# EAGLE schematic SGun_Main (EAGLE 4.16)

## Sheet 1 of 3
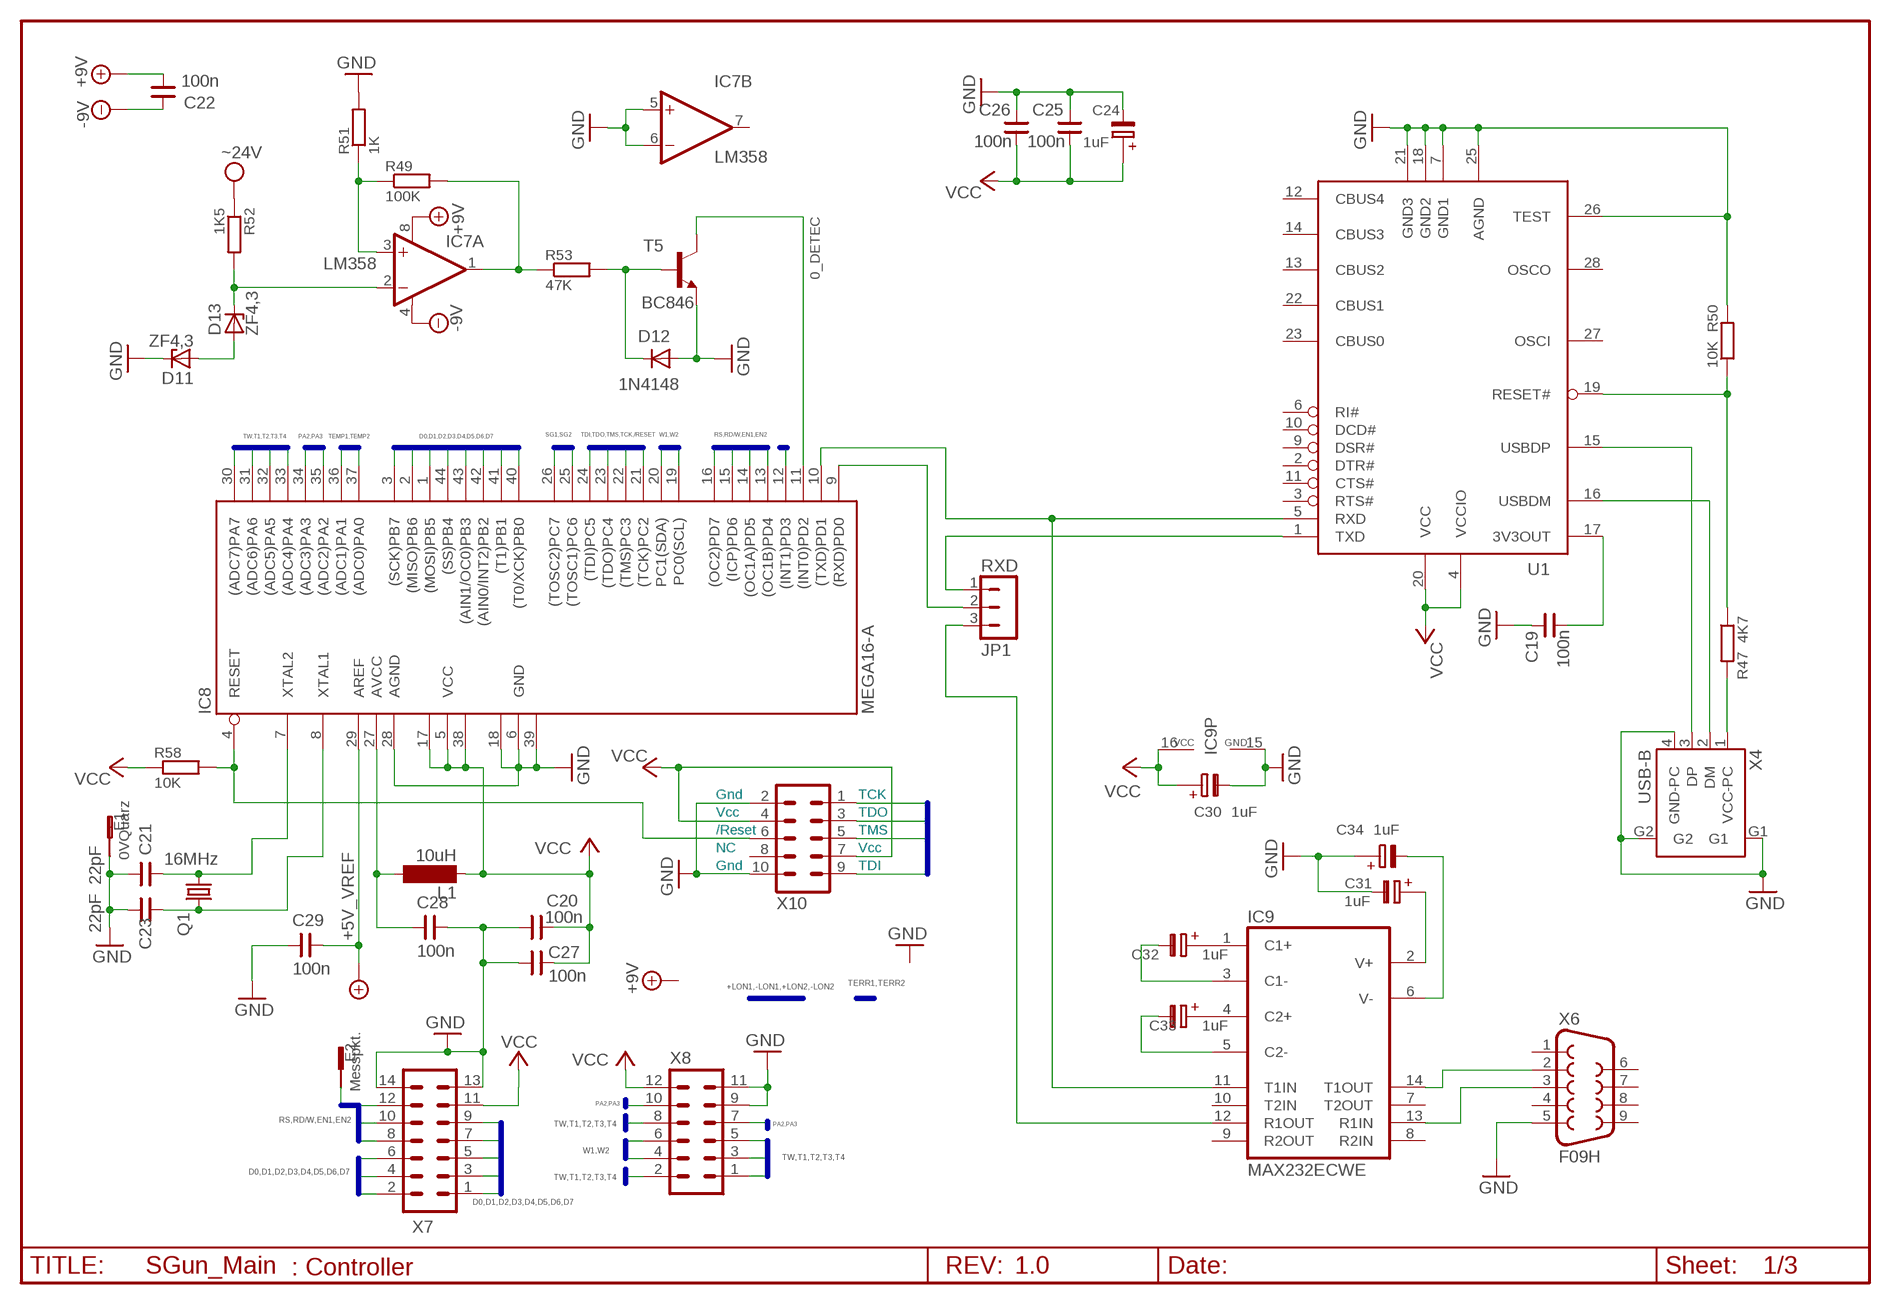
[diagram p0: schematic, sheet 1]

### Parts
C19  100n  CNP-0805  [0805]
C20  100n  CNP-0805  [0805]
C21  22pF  CNP-0805  [0805]
C22  100n  CNP-0805  [0805]
C23  22pF  CNP-0805  [0805]
C24  1uF  TT2D4  [TT2D4]
C25  100n  CNP-0805  [0805]
C26  100n  CNP-0805  [0805]
C27  100n  CNP-0805  [0805]
C28  100n  CNP-0805  [0805]
C29  100n  CNP-0805  [0805]
C30  1uF  TT2D4  [TT2D4]
C31  1uF  TT2D4  [TT2D4]
C32  1uF  TT2D4  [TT2D4]
C33  1uF  TT2D4  [TT2D4]
C34  1uF  TT2D4  [TT2D4]
D11  ZF4,3  ZDIODE_3.6_SMD  [DIODE]
D12  1N4148  [DIODE]
D13  ZF4,3  ZDIODE_3.6_SMD  [DIODE]
E1  0VQuarz  PIN1  [PIN1]
E2  Messpkt.  PIN1  [PIN1]
IC7  LM358  OPA2130U  [SO08]
IC8  MEGA16-A  [TQFP44]
IC9  MAX232ECWE  [SO16L]
L1  10uH  SM-0805  [SM-0805]
Q1  16MHz  CRYTALHC49U-V  [HC49U-V]
R47  4K7  R-SMD-1206  [R-SMD-1206]
R49  100K  R-SMD-1206  [R-SMD-1206]
R50  10K  R-SMD-1206  [R-SMD-1206]
R51  1K  R-SMD-1206  [R-SMD-1206]
R52  1K5  R-SMD-1206  [R-SMD-1206]
R53  47K  R-SMD-1206  [R-SMD-1206]
R58  10K  R-SMD-1206  [R-SMD-1206]
RXD  JP1  JP3Y  [JP3Y]
T5  BC846  [SOT23]
U1  FT232RL  [SSOP28DB]
X4  USB-B  [USB-B]
X6  F09H  [F09H]
X7  ST14-2.54  [ST14-2.54D]
X8  ST12-2.54D  [ST12-2.54D]
X10  ST10-2.54D  [ST10-2.54D]

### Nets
0_DETEC: IC8.11((INT0)PD2) T5.3(C)
+5V: C29.2 IC8.29(AREF) ; supply symbol labelled +5V_VREF ; also sheet 2,3
+9V: C22.1 IC7.8(A:V+) ; also sheet 2,3
-9V: C22.2 IC7.4(A:V-) ; also sheet 2,3
/RESET: IC8.4(RESET) R58.2 X10.6
D0: IC8.40((T0/XCK)PB0) X7.3
D1: IC8.41((T1)PB1) X7.1
D2: IC8.42((AIN0/INT2)PB2) X7.2
D3: IC8.43((AIN1/OC0)PB3) X7.4
D4: IC8.44((SS)PB4) X7.6
D5: IC8.1((MOSI)PB5) X7.5
D6: IC8.2((MISO)PB6) X7.7
D7: IC8.3((SCK)PB7) X7.9
EN1: IC8.16((OC2)PD7) X7.8
EN2: E2.1(-) IC8.15((ICP)PD6)
GND: C19.2 C20.1 C21.1 C23.1 C24.- C25.2 C26.2 C27.1 C28.2 C29.1 C30.- C31.- C34.+ D11.-(C) D12.+(A) E1.1(-) IC7.5(B:+IN) IC7.6(B:-IN) IC8.6(GND) IC8.18(GND1) IC8.28(AGND) IC8.39(GND2) IC9.15(GND) R50.2 R51.2 T5.2(E) U1.7(GND1) U1.18(GND2) U1.21(GND3) U1.25(AGND) U1.26(TEST) X4.4(GND-PC) X4.G1 X4.G2 X6.5 X7.13 X7.14 X8.9 X8.11 X10.2 X10.10 ; also sheet 2,3
N$1: D13.-(C) IC7.2(A:-IN) R52.2
N$2: U1.16(USBDM) X4.2(DM)
N$3: D11.+(A) D13.+(A)
N$4: IC7.3(A:+IN) R49.1 R51.1
N$5: IC7.1(A:OUT) R49.2 R53.1
N$6: U1.15(USBDP) X4.3(DP)
N$7: C32.+ IC9.1(C1+)
N$8: C33.+ IC9.4(C2+)
N$9: C32.- IC9.3(C1-)
N$10: C33.- IC9.5(C2-)
N$11: C31.+ IC9.2(V+)
N$12: C34.- IC9.6(V-)
N$14: C19.1 U1.17(3V3OUT)
N$15: IC8.9((RXD)PD0) RXD.2
N$16: IC9.14(T1OUT) X6.2
N$17: IC9.13(R1IN) X6.3
N$19: C28.1 IC8.27(AVCC) L1.2
N$23: R47.1 R50.1 U1.19(RESET#)
N$25: C21.2 IC8.7(XTAL2) Q1.1
N$26: C23.2 IC8.8(XTAL1) Q1.2
N$27: R47.2 X4.1(VCC-PC)
N$37: D12.-(C) R53.2 T5.1(B)
N$76: RXD.1 U1.1(TXD)
PA2: IC8.35((ADC2)PA2) X8.10
PA3: IC8.34((ADC3)PA3) X8.7
RD/W: IC8.14((OC1A)PD5) X7.10
RS: IC8.13((OC1B)PD4) X7.12
RXD: IC9.12(R1OUT) RXD.3
SG1: IC8.25((TOSC1)PC6) ; also sheet 3
SG2: IC8.26((TOSC2)PC7) ; also sheet 3
T1: IC8.33((ADC4)PA4) X8.1
T2: IC8.32((ADC5)PA5) X8.3
T3: IC8.31((ADC6)PA6) X8.5
T4: IC8.30((ADC7)PA7) X8.2
TCK: IC8.21((TCK)PC2) X10.1
TDI: IC8.24((TDI)PC5) X10.9
TDO: IC8.23((TDO)PC4) X10.3
TEMP1: IC8.37((ADC0)PA0) ; also sheet 2
TEMP2: IC8.36((ADC1)PA1) ; also sheet 2
TMS: IC8.22((TMS)PC3) X10.5
TW: IC8.12((INT1)PD3) X8.8
TXD: IC8.10((TXD)PD1) IC9.11(T1IN) U1.5(RXD)
VCC: C20.2 C24.+ C25.1 C26.1 C27.2 C30.+ IC8.5(VCC) IC8.17(VCC1) IC8.38(VCC2) IC9.16(VCC) L1.1 R58.1 U1.4(VCCIO) U1.20(VCC) X7.11 X8.12 X10.4 X10.7 ; also sheet 3
VPP: R52.1 ; supply symbol labelled ~24V ; also sheet 3
W1: IC8.19(PC0(SCL)) X8.4
W2: IC8.20(PC1(SDA)) X8.6
Unconnected: IC7.7(B:OUT) IC9.7(T2OUT) IC9.8(R2IN) IC9.9(R2OUT) IC9.10(T2IN) U1.2(DTR#) U1.3(RTS#) U1.6(RI#) U1.9(DSR#) U1.10(DCD#) U1.11(CTS#) U1.12(CBUS4) U1.13(CBUS2) U1.14(CBUS3) U1.22(CBUS1) U1.23(CBUS0) U1.27(OSCI) U1.28(OSCO) X6.1 X6.4 X6.6 X6.7 X6.8 X6.9 X10.8

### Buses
TDI,TDO,TMS,TCK,/RESET
D0,D1,D2,D3,D4,D5,D6,D7
RS,RD/W,EN1,EN2
TW,T1,T2,T3,T4
SG1,SG2
W1,W2
TEMP1,TEMP2
TERR1,TERR2
+LON1,-LON1,+LON2,-LON2
PA2,PA3

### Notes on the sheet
- Gnd | TCK
- Vcc | TDO
- /Reset | TMS
- NC | Vcc
- Gnd | TDI
- : Controller | 1.0

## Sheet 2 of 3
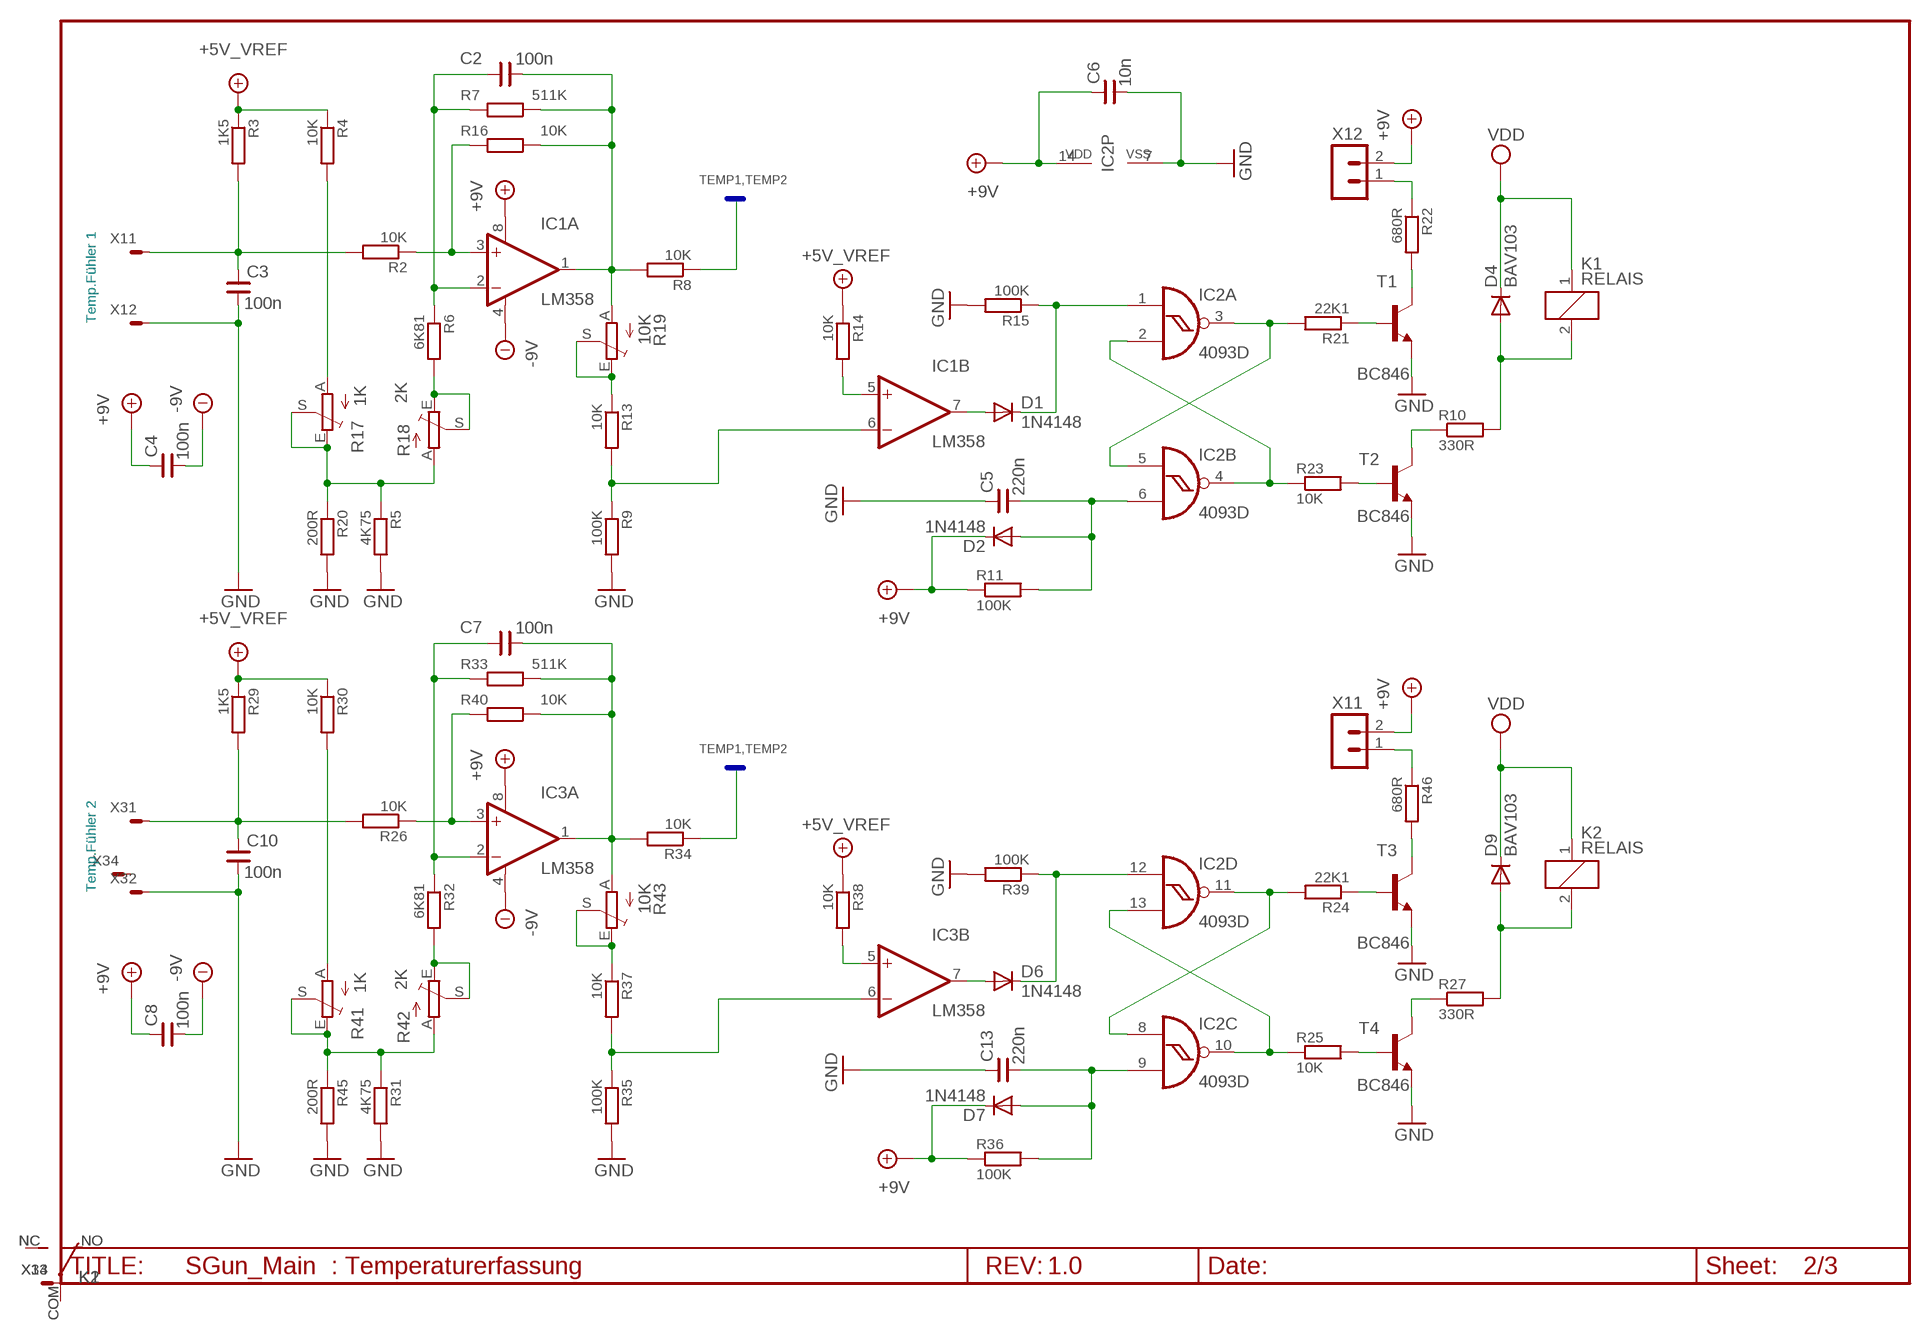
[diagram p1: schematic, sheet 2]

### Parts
C2  100n  CNP-0805  [0805]
C3  100n  CNP-0805  [0805]
C4  100n  CNP-0805  [0805]
C5  220n  CNP-0805  [0805]
C6  10n  CNP-0805  [0805]
C7  100n  CNP-0805  [0805]
C8  100n  CNP-0805  [0805]
C10  100n  CNP-0805  [0805]
C13  220n  CNP-0805  [0805]
D1  1N4148  [DIODE]
D2  1N4148  [DIODE]
D4  BAV103  1N4148  [DIODE]
D6  1N4148  [DIODE]
D7  1N4148  [DIODE]
D9  BAV103  1N4148  [DIODE]
IC1  LM358  OPA2130U  [SO08]
IC2  4093D  [SO14]
IC3  LM358  OPA2130U  [SO08]
K1  RELAIS  PE30PE-FORM-D  [PE-FORM-D]
K2  RELAIS  PE30PE-FORM-D  [PE-FORM-D]
R2  10K  R-SMD-1206  [R-SMD-1206]
R3  1K5  R-SMD-1206  [R-SMD-1206]
R4  10K  R-SMD-1206  [R-SMD-1206]
R5  4K75  R-SMD-1206  [R-SMD-1206]
R6  6K81  R-SMD-1206  [R-SMD-1206]
R7  511K  R-SMD-1206  [R-SMD-1206]
R8  10K  R-SMD-1206  [R-SMD-1206]
R9  100K  R-SMD-1206  [R-SMD-1206]
R10  330R  R-SMD-1206  [R-SMD-1206]
R11  100K  R-SMD-1206  [R-SMD-1206]
R13  10K  R-SMD-1206  [R-SMD-1206]
R14  10K  R-SMD-1206  [R-SMD-1206]
R15  100K  R-SMD-1206  [R-SMD-1206]
R16  10K  R-SMD-1206  [R-SMD-1206]
R17  1K  TRIM_EU-S64W  [S64W]
R18  2K  TRIM_EU-S64W  [S64W]
R19  10K  TRIM_EU-S64W  [S64W]
R20  200R  R-SMD-1206  [R-SMD-1206]
R21  22K1  R-SMD-1206  [R-SMD-1206]
R22  680R  R-SMD-1206  [R-SMD-1206]
R23  10K  R-SMD-1206  [R-SMD-1206]
R24  22K1  R-SMD-1206  [R-SMD-1206]
R25  10K  R-SMD-1206  [R-SMD-1206]
R26  10K  R-SMD-1206  [R-SMD-1206]
R27  330R  R-SMD-1206  [R-SMD-1206]
R29  1K5  R-SMD-1206  [R-SMD-1206]
R30  10K  R-SMD-1206  [R-SMD-1206]
R31  4K75  R-SMD-1206  [R-SMD-1206]
R32  6K81  R-SMD-1206  [R-SMD-1206]
R33  511K  R-SMD-1206  [R-SMD-1206]
R34  10K  R-SMD-1206  [R-SMD-1206]
R35  100K  R-SMD-1206  [R-SMD-1206]
R36  100K  R-SMD-1206  [R-SMD-1206]
R37  10K  R-SMD-1206  [R-SMD-1206]
R38  10K  R-SMD-1206  [R-SMD-1206]
R39  100K  R-SMD-1206  [R-SMD-1206]
R40  10K  R-SMD-1206  [R-SMD-1206]
R41  1K  TRIM_EU-S64W  [S64W]
R42  2K  TRIM_EU-S64W  [S64W]
R43  10K  TRIM_EU-S64W  [S64W]
R45  200R  R-SMD-1206  [R-SMD-1206]
R46  680R  R-SMD-1206  [R-SMD-1206]
T1  BC846  [SOT23]
T2  BC846  [SOT23]
T3  BC846  [SOT23]
T4  BC846  [SOT23]
X1  G381-4  [G381-4]
X3  G381-4  [G381-4]
X11  ST2-254  [ST2-254]
X12  ST2-254  [ST2-254]

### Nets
+5V: R3.1 R4.1 R14.1 R29.1 R30.1 R38.1 ; supply symbol labelled +5V_VREF ; also sheet 1,3
+9V: C4.1 C6.1 C8.1 D2.-(C) D7.-(C) IC1.8(A:V+) IC2.14(P:VDD) IC3.8(A:V+) R11.1 R36.1 X11.2 X12.2 ; also sheet 1,3
-9V: C4.2 C8.2 IC1.4(A:V-) IC3.4(A:V-) ; also sheet 1,3
GND: C3.2 C5.1 C6.2 C10.2 C13.1 IC2.7(P:VSS) R5.2 R9.2 R15.2 R20.2 R31.2 R35.2 R39.2 R45.2 T1.2(E) T2.2(E) T3.2(E) T4.2(E) X1.2 X3.2 ; also sheet 1,3
IC8: IC2.3(A:O) IC2.5(B:I0) R21.2
N$13: R22.1 X12.1
N$18: R13.1 R19.E R19.S
N$24: R46.1 X11.1
N$28: IC2.8(C:I0) IC2.11(D:O) R24.2
N$29: IC2.10(C:O) IC2.13(D:I1) R25.1
N$36: IC1.5(B:+IN) R14.2
N$38: R4.2 R17.A
N$40: R5.1 R17.E R17.S R18.A R20.1
N$41: R6.2 R18.E R18.S
N$42: C3.1 R2.2 R3.2 X1.1
N$43: C2.1 IC1.2(A:-IN) R6.1 R7.2
N$44: IC1.3(A:+IN) R2.1 R16.2
N$45: C2.2 IC1.1(A:OUT) R7.1 R8.2 R16.1 R19.A
N$46: R31.1 R41.E R41.S R42.A R45.1
N$47: IC1.6(B:-IN) R9.1 R13.2
N$48: D1.+(A) IC1.7(B:OUT)
N$49: D1.-(C) IC2.1(A:I0) R15.1
N$50: IC2.2(A:I1) IC2.4(B:O) R23.1
N$52: C5.2 D2.+(A) IC2.6(B:I1) R11.2
N$53: R10.1 T2.3(C)
N$54: R21.1 T1.1(B)
N$55: R22.2 T1.3(C)
N$56: D4.+(A) K1.2 R10.2
N$57: R30.2 R41.A
N$59: R32.2 R42.E R42.S
N$60: C7.1 IC3.2(A:-IN) R32.1 R33.2
N$61: C10.1 R26.2 R29.2 X3.1
N$62: IC3.3(A:+IN) R26.1 R40.2
N$63: C7.2 IC3.1(A:OUT) R33.1 R34.2 R40.1 R43.A
N$65: IC3.6(B:-IN) R35.1 R37.2
N$66: IC3.5(B:+IN) R38.2
N$67: D6.+(A) IC3.7(B:OUT)
N$68: D6.-(C) IC2.12(D:I0) R39.1
N$71: C13.2 D7.+(A) IC2.9(C:I1) R36.2
N$72: R24.1 T3.1(B)
N$73: R46.2 T3.3(C)
N$74: R27.1 T4.3(C)
N$75: D9.+(A) K2.2 R27.2
N$91: R23.2 T2.1(B)
N$92: R25.2 T4.1(B)
N$93: R37.1 R43.E R43.S
TEMP1: R8.1 ; also sheet 1
TEMP2: R34.1 ; also sheet 1
VDD: D4.-(C) D9.-(C) K1.1 K2.1 ; also sheet 3

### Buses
TEMP1,TEMP2

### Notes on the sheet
- Temp.Fühler 1
- Temp.Fühler 2
- : Temperaturerfassung | 1.0

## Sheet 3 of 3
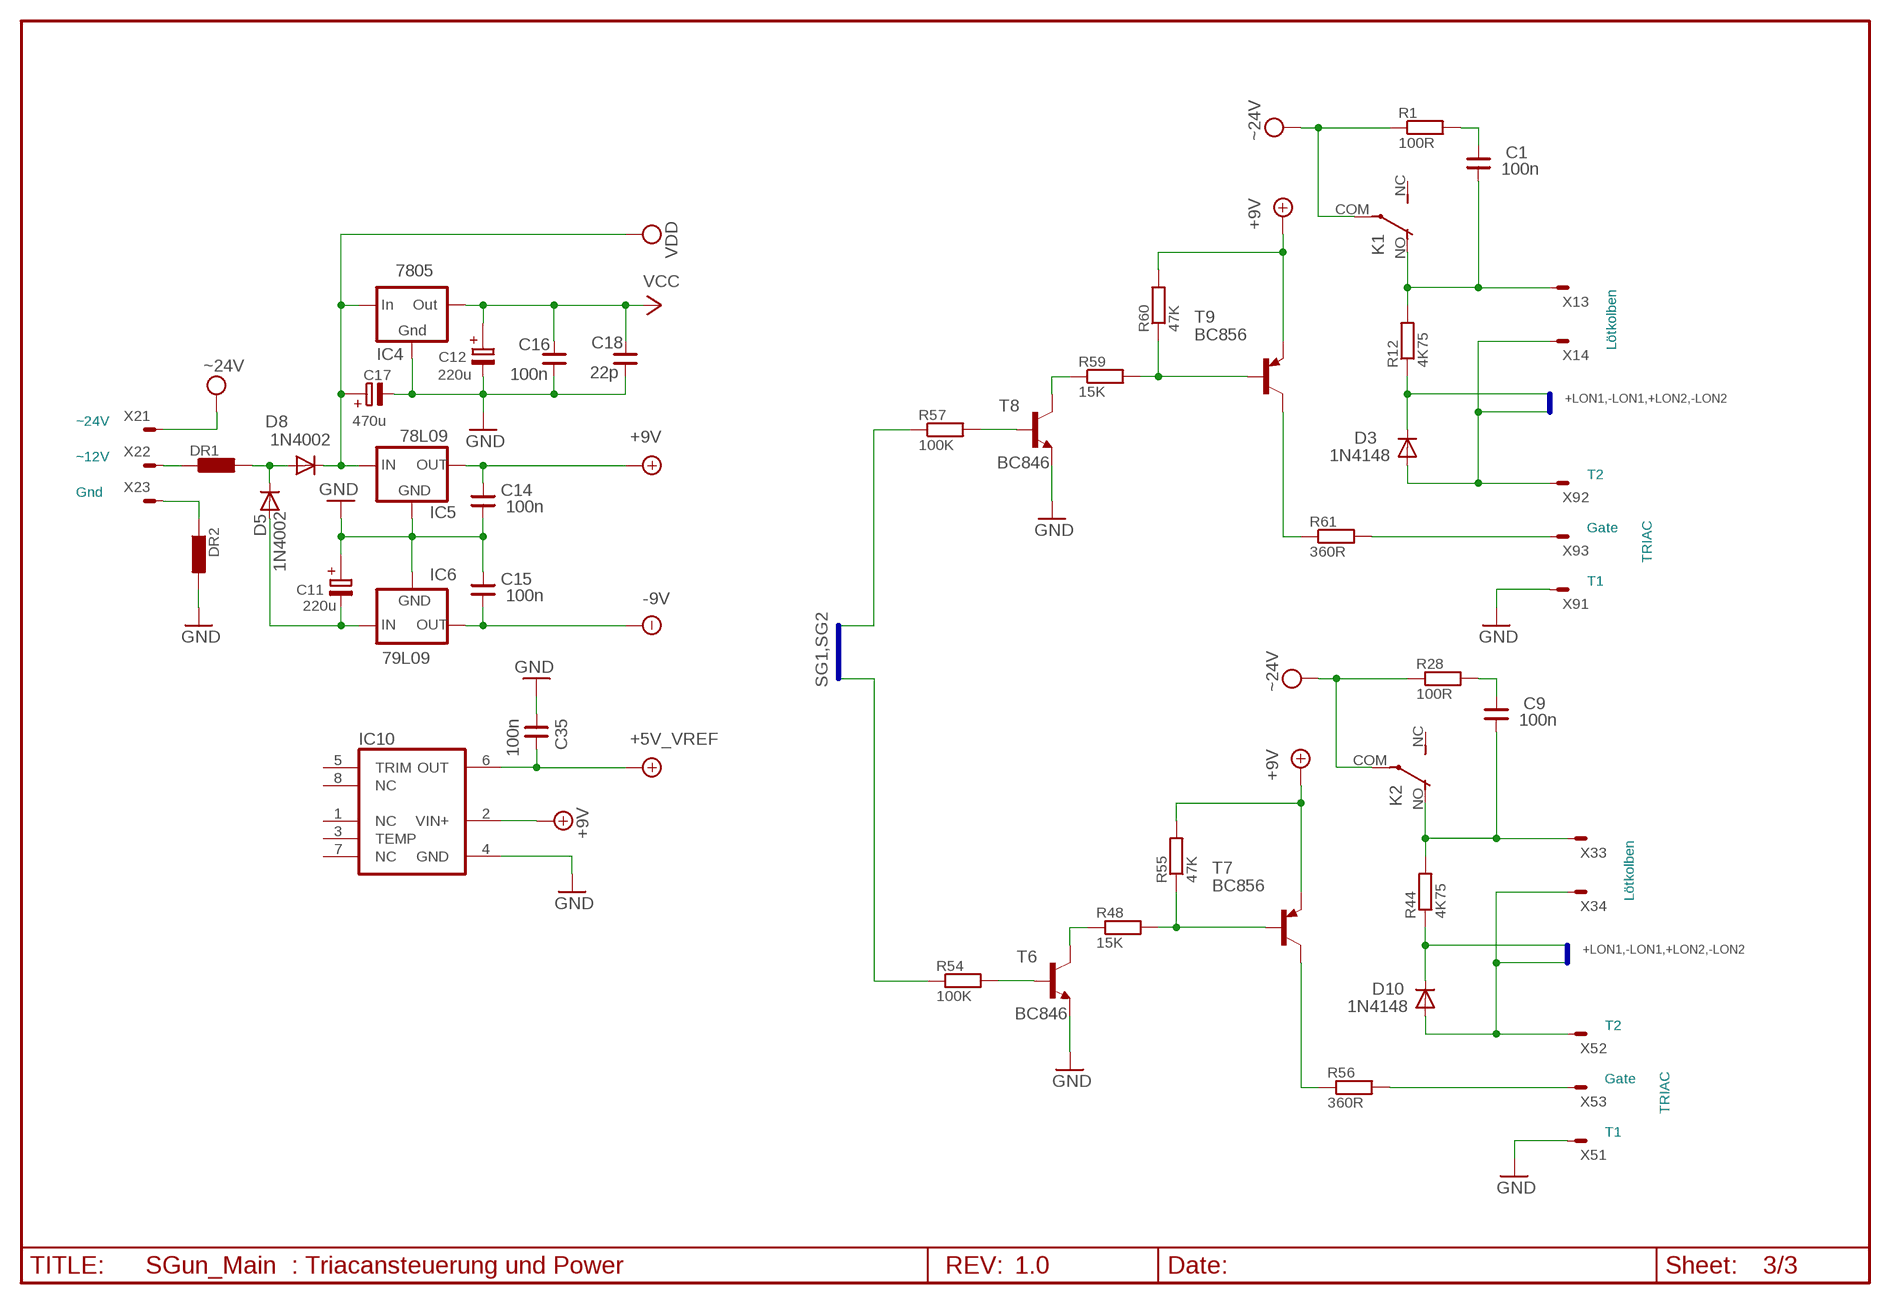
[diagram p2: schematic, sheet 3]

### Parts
C1  100n  CNP-0805  [0805]
C9  100n  CNP-0805  [0805]
C11  220u  TT5D11  [TT5D11]
C12  220u  TT5D11  [TT5D11]
C14  100n  CNP-0805  [0805]
C15  100n  CNP-0805  [0805]
C16  100n  CNP-0805  [0805]
C17  470u  TT5D13  [TT5D13]
C18  22p  CNP-0805  [0805]
C35  100n  CNP-0805  [0805]
D3  1N4148  [DIODE]
D5  1N4002  1N400X_SMD  [DIODE_SMD_5.0]
D8  1N4002  1N400X_SMD  [DIODE_SMD_5.0]
D10  1N4148  [DIODE]
DR1  DROSSEL10  [DROSSEL1]
DR2  DROSSEL10  [DROSSEL1]
IC4  7805  SP.REGLER-SMD  [DPACK]
IC5  78L09  78LXX  [78LXX]
IC6  79L09  79LXX  [79LXX]
IC10  REF02SO08  [SO08]
R1  100R  R-SMD-1206  [R-SMD-1206]
R12  4K75  R-SMD-1206  [R-SMD-1206]
R28  100R  R-SMD-1206  [R-SMD-1206]
R44  4K75  R-SMD-1206  [R-SMD-1206]
R48  15K  R-SMD-1206  [R-SMD-1206]
R54  100K  R-SMD-1206  [R-SMD-1206]
R55  47K  R-SMD-1206  [R-SMD-1206]
R56  360R  R-SMD-1206  [R-SMD-1206]
R57  100K  R-SMD-1206  [R-SMD-1206]
R59  15K  R-SMD-1206  [R-SMD-1206]
R60  47K  R-SMD-1206  [R-SMD-1206]
R61  360R  R-SMD-1206  [R-SMD-1206]
T6  BC846  [SOT23]
T7  BC856  BC856ASMD  [SOT23-BEC]
T8  BC846  [SOT23]
T9  BC856  BC856ASMD  [SOT23-BEC]
X2  G381-3  [G381-3]
X5  G381-3  [G381-3]
X9  G381-3  [G381-3]

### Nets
+5V: C35.2 IC10.6(OUT) ; supply symbol labelled +5V_VREF ; also sheet 1,2
+9V: C14.2 IC5.OUT IC10.2(VIN+) R55.2 R60.2 T7.E T9.E ; also sheet 1,2
+LON1: D3.-(C) R12.1
+LON2: D10.-(C) R44.1
-9V: C15.1 IC6.OUT ; also sheet 1,2
-LON1: D3.+(A) X1.4 X9.2
-LON2: D10.+(A) X3.4 X5.2
GND: C11.+ C12.- C14.1 C15.2 C16.1 C17.- C18.1 C35.1 DR2.2 IC4.2(GND) IC5.GND IC6.GND IC10.4(GND) T6.2(E) T8.2(E) X5.1 X9.1 ; also sheet 1,2
N$20: DR1.1 X2.2
N$21: DR2.1 X2.3
N$22: D5.-(C) D8.+(A) DR1.2
N$39: C11.- D5.+(A) IC6.IN
N$77: R57.2 T8.1(B)
N$78: R59.1 T8.3(C)
N$79: R59.2 R60.1 T9.B
N$80: R61.1 T9.C
N$81: R61.2 X9.3
N$82: C1.2 R1.2
N$84: R54.2 T6.1(B)
N$85: R48.1 T6.3(C)
N$86: R48.2 R55.1 T7.B
N$87: R56.1 T7.C
N$88: R56.2 X5.3
N$89: C9.2 R28.2
N$90: C9.1 K2.NO(2:O) R44.2 X3.3
SG1: R57.1 ; also sheet 1
SG2: R54.1 ; also sheet 1
VCC: C12.+ C16.2 C18.2 IC4.3(OUT) ; also sheet 1
VDD: C17.+ D8.-(C) IC4.1(IN) IC5.IN ; also sheet 2
VPP: K1.COM(2:P) K2.COM(2:P) R1.1 R28.1 X2.1 ; supply symbol labelled ~24V ; also sheet 1
VPP1: C1.1 K1.NO(2:O) R12.2 X1.3
Unconnected: IC10.1(NC) IC10.3(TEMP) IC10.5(TRIM) IC10.7(NC) IC10.8(NC) K1.NC(2:S) K2.NC(2:S)

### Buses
SG1,SG2
+LON1,-LON1,+LON2,-LON2

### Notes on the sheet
- Lötkolben
- ~24V
- ~12V
- T2
- Gnd
- TRIAC
- Gate
- T1
- Lötkolben
- T2
- TRIAC
- Gate
- T1
- : Triacansteuerung und Power | 1.0

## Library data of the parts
C1-C10 C13-C16 C18-C23 C25-C29 C35 = cap-master:CNP-: NON-POLARIZED CAP
C11 C12 = CAP-TANT:TT5D11
C17 = CAP-TANT:TT5D13
C24 C30-C34 = CAP-TANT:TT2D4
D1-D4 D6 D7 D9 D10 D12 = ANDY:1N4148
D5 D8 = ANDY:1N400X_SMD
D11 D13 = ANDY:ZDIODE_3.6_SMD
DR1 DR2 = ANDY:DROSSEL10
E1 E2 = ANDY:PIN1
IC1 IC3 IC7 = burr-brown:OPA2130: Operational Amplifier
IC2 = 40xx:4093: Quad 2-input NAND schmitt trigger
IC4 = ANDY-SMD:SP.REGLER-SMD
IC5 = v-reg:78LXX: VOLTAGE REGULATOR
IC6 = v-reg:79LXX: VOLTAGE REGULATOR
IC8 = atmel:MEGA16: MICROCONTROLLER 16 Kbytes FLASH 1 kbytes SRAM 512 bytes EEPROM USART 8-channel 10 bit ADC Source: avr.lbr
IC9 = maxim:MAX232ECWE: RS232 TRANSEIVER
IC10 = burr-brown:REF02
K1 K2 = relay:PE30?*: SLIM POWER Relay NAiS Source: http://www.mew-europe.com/.. en_ds_61122_0000.pdf
L1 = inductor-neosid:SM-0805
Q1 = crystal:CRYTAL: CRYSTAL
R1-R16 R20-R40 R44-R61 = ANDY-SMD:R-SMD-1206
R17-R19 R41-R43 = pot:TRIM_EU-: POTENTIOMETER
RXD = JUMPS:JP3Y
T1-T6 T8 = transistor:BC846: NPN TRANSISTOR
T7 T9 = transistor-pnp:BC856*: PNP Transistror
U1 = ftdichip-3:FT232RL: USB UART 4th Generation USB UART (USB <-> Serial) Controller
X1 X3 = ANDY:G381-4
X2 X5 X9 = ANDY:G381-3
X4 = ANDY:USB-B
X6 = SUBD:F09H
X7 = ANDY:ST14-2.54
X8 = ANDY:ST12-2.54D
X10 = ANDY:ST10-2.54D
X11 X12 = ANDY:ST2-254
